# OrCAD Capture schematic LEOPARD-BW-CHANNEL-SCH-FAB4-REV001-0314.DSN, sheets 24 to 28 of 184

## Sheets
24 155_PVTT_CD_MOSFET: size A3; title: PVTT_CD_MOSFET
25 154_PVDDQ_CD_MOSFET: size C; title: PVDDQ_CD_MOSFET
26 153_PVDDQ_CD_Controller: size C; title: PVDDQ_CD_CONTROLLER
27 152_PVPP_AB_TPS53318: size A3; title: PVPP_AB_TPS53318
28 151_PVDDQ_AB_Decoupling: size A3; title: PVDDQ_AB_DECOUPLING

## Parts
sheet 151_PVDDQ_AB_Decoupling
PC285  SCD1U25V5KX-1GP  [C805H54]
PC286  SC1U25V6KX-2GP  [C1206H45]
PC287  SCD1U25V5KX-1GP  [C805H54]
PC288  SE470UF2VDM-GP  [CT7343H83]
PC289  SE470UF2VDM-GP  [CT7343H83]
PC290  SE470UF2VDM-GP  [CT7343H83]
PC291  SE470UF2VDM-GP  [CT7343H83]
PC292  SC47U4V5MX-2-GP  [C805H58]
PC293  SC47U4V5MX-2-GP  [C805H58]
PC294  SC47U4V5MX-2-GP  [C805H58]
PC295  SC47U4V5MX-2-GP  [C805H58]
PC296  SC22U6D3V5MX-5-GP  [C805H56]
PC297  SC22U6D3V5MX-5-GP  [C805H56]
PC298  SC22U6D3V5MX-5-GP  [C805H56]
PC299  SC22U6D3V5MX-5-GP  [C805H56]
PC300  SC22U6D3V5MX-5-GP  [C805H56]
PC301  SC22U6D3V5MX-5-GP  [C805H56]
PC302  SC22U6D3V5MX-5-GP  [C805H56]
PC303  SC22U6D3V5MX-5-GP  [C805H56]
PC304  SC22U6D3V5MX-5-GP  [C805H56]
PC305  SC22U6D3V5MX-5-GP  [C805H56]
PC306  SC22U6D3V5MX-5-GP  [C805H56]
PC307  SC22U6D3V5MX-5-GP  [C805H56]
PC308  SC22U6D3V5MX-5-GP  [C805H56]
PC309  SC22U6D3V5MX-5-GP  [C805H56]
PC310  SC22U6D3V5MX-5-GP  [C805H56]
PC311  SC22U6D3V5MX-5-GP  [C805H56]
PC312  SC22U6D3V5MX-5-GP  [C805H56]
PC313  SC22U6D3V5MX-5-GP  [C805H56]
PC314  SC22U6D3V5MX-5-GP  [C805H56]
PC315  SC22U6D3V5MX-5-GP  [C805H56]
PC316  SC22U6D3V5MX-5-GP  [C805H56]
PC317  SC22U6D3V5MX-5-GP  [C805H56]
PC318  SC22U6D3V5MX-5-GP  [C805H56]
PC319  SC22U6D3V5MX-5-GP  [C805H56]
PC320  SC22U6D3V5MX-5-GP  [C805H56]
PC321  SC22U6D3V5MX-5-GP  [C805H56]
PC322  SC22U6D3V5MX-5-GP  [C805H56]
PC323  SC22U6D3V5MX-5-GP  [C805H56]
PC324  SC22U6D3V5MX-5-GP  [C805H56]
PC325  SC22U6D3V5MX-5-GP  [C805H56]
PC326  SC22U6D3V5MX-5-GP  [C805H56]
PC327  SC22U6D3V5MX-5-GP  [C805H56]
PC328  SC22U6D3V5MX-5-GP  [C805H56]
PC329  SC22U6D3V5MX-5-GP  [C805H56]
PC330  SC22U6D3V5MX-5-GP  [C805H56]
PC331  SC22U6D3V5MX-5-GP  [C805H56]
PC332  SC22U6D3V5MX-5-GP  [C805H56]
PC333  SC22U6D3V5MX-5-GP  [C805H56]
PC334  SC22U6D3V5MX-5-GP  [C805H56]
PC335  SC22U6D3V5MX-5-GP  [C805H56]
PC837  SC22U6D3V5MX-5-GP  [C805H56]
PC838  SC22U6D3V5MX-5-GP  [C805H56]
PC839  SC22U6D3V5MX-5-GP  [C805H56]
PC840  SC22U6D3V5MX-5-GP  [C805H56]
PC841  SC22U6D3V5MX-5-GP  [C805H56]
PC842  SC22U6D3V5MX-5-GP  [C805H56]
PC843  SC22U6D3V5MX-5-GP  [C805H56]
PC844  SC22U6D3V5MX-5-GP  [C805H56]
PC994  SC22U6D3V5MX-5-GP  [C805H56]
PC995  SC22U6D3V5MX-5-GP  [C805H56]
PC996  SC22U6D3V5MX-5-GP  [C805H56]
PL16  IND-65NH-GP  [L4038-1412H158]
PR181  33R3F-L-GP  [R603H22]
PR182  0R2F-L-GP  [R402H16]
PR183  0R2F-L-GP  [R402H16]
PTC5  E270U16VM-28-GP  [ECAP-100D6D3H363]
sheet 152_PVPP_AB_TPS53318
PC336  SC10U16V5KX-1-GP  [C805H54]
PC337  SC10U16V5KX-1-GP  [C805H54]
PC338  SC10U16V5KX-1-GP  [C805H54]
PC339  SC10U16V5KX-1-GP  [C805H54]
PC340  SCD1U16V3KX-3GP  [C603H36]
PC341  SC4D7U25V5KX-1-GP  [C805H58]
PC342  SCD1U50V3KX-GP  [C603H36]
PC343  SC2K2P50V3KX-GP  [C603]
PC344  SC1U10V2KX-4-GP  [C402H22]
PC345  SCD1U16V2KX-3GP  [C402H22]
PC346  SC1KP50V2KX-1GP  [C402H22]
PC347  SCD1U16V3KX-3GP  [C603H36]
PC348  SC22U6D3V5MX-5-GP  [C805H56]
PC349  SC47U4V5MX-2-GP  [C805H58]
PC350  SC47U4V5MX-2-GP  [C805H58]
PC351  SC47U4V5MX-2-GP  [C805H58]
PC352  SC47U4V5MX-2-GP  [C805H58]
PC353  SC47U4V5MX-2-GP  [C805H58]
PC354  SC47U4V5MX-2-GP  [C805H58]
PC1035  SC1U10V2KX-4-GP  [C402H22]
PD22  BZT52-C3V3S-GP  [SOD323AKH38]
PL17  BLM21PG220SN1DGP  [L20125H42]
PL18  IND-2D2UH-242-GP  [L7165-1732H119]
PR184  2D2R3-1-U-GP  [R603H22]
PR185  3D01R5F-GP  [R805H24]
PR186  0R2J-2-GP  [R402H16]
PR188  3K9R2F-GP  [R402H16]
PR189  10R3F-GP  [R603H22]
PR190  100KR2F-L1-GP  [R402H16]
PR191  3D01R5F-GP  [R805H24]
PR192  100KR2F-L1-GP  [R402H16]
PR193  100KR2F-L1-GP  [R402H16]
PR194  866KR2F-GP  [R402H16]
PR195  619KR2F-GP  [R402H16]
PR196  31K6R2F-GP  [R402H16]
PR197  10KR2F-2-GP  [R402H16]
PR198  0R3J-0-U-GP  [R603H22]
PR643  10KR2F-2-GP  [R402H16]
PR798  0R2J-2-GP  [R402H16]
PU18  TPS53318DQPR-GP  [DFN22G6050-G6133H60]
sheet 153_PVDDQ_CD_Controller
PC1389  SC1KP50V2KX-1GP  [C402H22]
PC1390  SC1U10V2KX-4-GP  [C402H22]
PC1391  SCD1U16V2KX-3GP  [C402H22]
PC1392  SC1U10V2KX-4-GP  [C402H22]
PC1393  SCD1U16V2KX-3GP  [C402H22]
PC1397  SC220P50V2KX-3GP  [C402H22]
PC1398  SCD47U25V3KX-3-GP  [C603H36]
PC1399  SC10U4V3MX-3-GP  [C603H40]
PC1400  SC220P50V2KX-3GP  [C402H22]
PC1401  SCD1U16V2KX-3GP  [C402H22]
PC1402  SC220P50V2JN-3GP  [C402H22]
PC1467  SC220P50V2JN-3GP  [C402H22]
PC1621  SC220P50V2JN-3GP  [C402H22]
PC7333  SCD47U6D3V2KX-1-GP  [C402H22]
PC7334  SCD47U6D3V2KX-1-GP  [C402H22]
PQ12  NST3906F3T5G-GP-U  [SOT-1123CBE1006-1H16]
PR1939  0R2J-2-GP  [R402H16]
PR2023  19K1R2F-GP  [R402H16]
PR2024  1KR2F-3-GP  [R402H16]
PR2025  0R2J-2-GP  [R402H16]
PR2030  1KR2F-3-GP  [R402H16]
PR2031  1KR2F-3-GP  [R402H16]
PR2032  0R2J-2-GP  [R402H16]
PR2033  0R2J-2-GP  [R402H16]
PR2034  10R3F-GP  [R603H22]
PR2036  0R2J-2-GP  [R402H16]
PR2037  0R0402-PAD-1-GP  [0R0402-PAD]
PR2040  16KR2F-GP  [R402H16]
PR2041  5K36R2F-GP  [R402H16]
PR2042  549R2F-GP  [R402H16]
PR2043  8K06R2F-GP  [R402H16]
PR2044  10R3F-GP  [R603H22]
PR2045  0R2J-2-GP  [R402H16]
PR2046  0R0402-PAD-1-GP  [0R0402-PAD]
PR2047  100R2F-L1-GP-U  [R402H14]
PR2048  100R2F-L1-GP-U  [R402H14]
PR2049  49D9R2F-GP  [R402H16]
PR2051  0R2J-2-GP  [R402H16]
PR2052  0R2J-2-GP  [R402H16]
PR2053  150R2F-1-GP  [R402H16]
PTP4  TP20B24R10-B-GP  [TP20B24R10-B]
PU19  PX3244HDM-1-GP  [QFN40J5-G3D75H36]
sheet 154_PVDDQ_CD_MOSFET
PC1526  SCD47U25V3KX-3-GP  [C603H36]
PC1527  SC10U16V5KX-1-GP  [C805H54]
PC1528  SC10U16V5KX-1-GP  [C805H54]
PC1529  SC10U16V5KX-1-GP  [C805H54]
PC1530  SCD1U16V2KX-3GP  [C402H22]
PC1531  SC1U25V3KX-GP  [C603H36]
PC1532  SCD1U16V2KX-3GP  [C402H22]
PC1533  SC1U10V2KX-4-GP  [C402H22]
PC1534  SCD22U16V2KX-GP  [C402H22]
PC1535  SC1U10V2KX-4-GP  [C402H22]
PC1536  SCD47U25V3KX-3-GP  [C603H36]
PC1537  SC10U16V5KX-1-GP  [C805H54]
PC1538  SC10U16V5KX-1-GP  [C805H54]
PC1539  SCD1U16V2KX-3GP  [C402H22]
PC1540  SC10U16V5KX-1-GP  [C805H54]
PC1541  SC1U25V3KX-GP  [C603H36]
PC1542  SCD1U16V2KX-3GP  [C402H22]
PC1543  SC1U10V2KX-4-GP  [C402H22]
PC1544  SCD22U16V2KX-GP  [C402H22]
PC1545  SC1U10V2KX-4-GP  [C402H22]
PG66  COPPER-CLOSE-GP-U  [CON2C-U]
PG70  COPPER-CLOSE-GP-U  [CON2C-U]
PG71  COPPER-CLOSE-GP-U  [CON2C-U]
PG72  COPPER-CLOSE-GP-U  [CON2C-U]
PL87  IND-150NH-15-GP  [L102078-254224H296]
PL94  IND-150NH-15-GP  [L102078-254224H296]
PR36  0R2J-2-GP  [R402H16]
PR37  0R2J-2-GP  [R402H16]
PR54  0R2J-2-GP  [R402H16]
PR55  0R2J-2-GP  [R402H16]
PR2211  1R2F-GP  [R402H16]
PR2244  1R2F-GP  [R402H16]
PR2245  10KR2F-2-GP  [R402H16]
PR2246  10KR2F-2-GP  [R402H16]
PR2267  0R3J-6-GP  [R603H22]
PR2270  0R3J-6-GP  [R603H22]
PR6651  562R2F-GP  [R402H16]
PR6652  562R2F-GP  [R402H16]
PR6665  562R2F-GP  [R402H16]
PR6666  562R2F-GP  [R402H16]
PTP31  TPAD24  [TPAD24]
PTP32  TPAD24  [TPAD24]
PTP45  TPAD24  [TPAD24]
PTP46  TPAD24  [TPAD24]
PU190  TDA21232-GP  [QFN31G5-G4P-7H38]
PU197  TDA21232-GP  [QFN31G5-G4P-7H38]
sheet 155_PVTT_CD_MOSFET
PC388  SC1U10V2KX-4-GP  [C402H22]
PC389  SCD22U16V2KX-GP  [C402H22]
PC391  SCD22U16V2KX-GP  [C402H22]
PC393  SC1U25V3KX-GP  [C603H36]
PC396  SC10U16V5KX-1-GP  [C805H54]
PC397  SC10U16V5KX-1-GP  [C805H54]
PC398  SCD47U25V3KX-3-GP  [C603H36]
PC399  SC220P50V2JN-3GP  [C402H22]
PC400  SC47U4V5MX-2-GP  [C805H58]
PC401  SC47U4V5MX-2-GP  [C805H58]
PC402  SC22U6D3V5MX-5-GP  [C805H56]
PC403  SC22U6D3V5MX-5-GP  [C805H56]
PC404  SC22U6D3V5MX-5-GP  [C805H56]
PC405  SC22U6D3V5MX-5-GP  [C805H56]
PC406  SC22U6D3V5MX-5-GP  [C805H56]
PC407  SC22U6D3V5MX-5-GP  [C805H56]
PC408  SC22U6D3V5MX-5-GP  [C805H56]
PC409  SC22U6D3V5MX-5-GP  [C805H56]
PC410  SC22U6D3V5MX-5-GP  [C805H56]
PC411  SC22U6D3V5MX-5-GP  [C805H56]
PC412  SC22U6D3V5MX-5-GP  [C805H56]
PC413  SC22U6D3V5MX-5-GP  [C805H56]
PC414  SE470UF2VDM-GP  [CT7343H83]
PG31  COPPER-CLOSE-GP-U  [CON2C-U]
PG32  COPPER-CLOSE-GP-U  [CON2C-U]
PL21  IND-1UH-101-GP  [L6868-3612H166]
PQ6  NST3906F3T5G-GP-U  [SOT-1123CBE1006-1H16]
PR244  2D2R2F-GP  [R402H16]
PR246  10KR2F-2-GP  [R402H16]
PR247  93K1R2F-L-GP  [R402H16]
PR250  562R2F-GP  [R402H16]
PR251  562R2F-GP  [R402H16]
PR252  0R2F-L-GP  [R402H16]
PR253  0R2F-L-GP  [R402H16]
PR254  120R3F-L-GP  [R603H22]
PR854  0R3J-0-U-GP  [R603H22]
PR855  0R3J-0-U-GP  [R603H22]
PU22  PX3517-GP  [DFN10G3-G2619H36]
PU23  AON7934-GP  [MLP8F3-G2P-1H32]

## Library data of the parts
PC285 PC287 = SCD1U25V5KX-1GP: CHIP CAP0.1U25V K0805 X7R(ROHS; GREENDFACTOR: R2_SA;HF_SA;G_SA;; Package Type: SMD-BCG; Part Number: 78.10422.21L; SPEC: http://wpqssvr.wistron.com.tw:7001/wpqs/servlet/COM.qpart.Attachment?PartNumber=78.10422.21L
PC286 = SC1U25V6KX-2GP: CHIP CAP C 1U 25V K1206 X7R; GREENDFACTOR: R2_SA;HF_SA;G_SA;; Package Type: SMD-BCG1; Part Number: 78.10522.22L; SPEC: http://wpqssvr.wistron.com.tw:7001/wpqs/servlet/COM.qpart.Attachment?PartNumber=78.10522.22L
PC288-PC291 PC414 = SE470UF2VDM-GP: CHIP CAP 470UF 2V EEFSX0D471X; GREENDFACTOR: R_SA;; Module: VR_DDR_P1V5_VDDQ; Package Type: SMD-TCG1; Part Number: 79.47719.2BL; Part Type: SMD-TCG1; Part_Function: Cout_bulk; Part_Spec: 470uF/2V/6mohm; Part_Type: Solid_al_cap; SPEC: http://wpqssvr.wistron.com.tw:7001/wpqs/servlet/COM.qpart.Attachment?PartNumber=79.47719.2BL; VENDOR_PN: EEFSX0D471XE
PC292-PC295 PC349-PC354 PC400 PC401 = SC47U4V5MX-2-GP: CHIP CAP C 47U 4V M0805 X6S; GREENDFACTOR: R2_SA;HF_SA;G_SA;; Package Type: SMD-BCG3; Part Number: 78.4761T.81L; SPEC: http://wpqssvr.wistron.com.tw:7001/wpqs/servlet/COM.qpart.Attachment?PartNumber=78.4761T.81L
PC296-PC335 PC348 PC402-PC413 PC837-PC844 = SC22U6D3V5MX-5-GP: CHIP CAP C 22U 6.3V M0805 X6S; GREENDFACTOR: R2_SA;HF_SA;G_SA;; Package Type: SMD-BCG2; Part Number: 78.22610.81L; SPEC: http://wpqssvr.wistron.com.tw:7001/wpqs/servlet/COM.qpart.Attachment?PartNumber=78.22610.81L
PC994-PC996 = SC22U6D3V5MX-5-GP: CHIP CAP C 22U 6.3V M0805 X6S; GREENDFACTOR: R2_SA;HF_SA;G_SA;; Package Type: SMD-BCG2; Part Number: 78.22610.81L; SPEC: http://wpqssvr.wistron.com.tw:7001/wpqs/servlet/COM.qpart.Attachment?PartNumber=78.22610.81L; Size: 0805; Type: X6S
PL16 = IND-65NH-GP: CHIP IND 65NH FP0404R1-R065-R; GREENDFACTOR: R2_SA;; Part Number: 68.650CN.101; Part Type: DISCRET-G6; SPEC: http://wpqssvr.wistron.com.tw:7001/wpqs/servlet/COM.qpart.Attachment?PartNumber=68.650CN.101
PR181 = 33R3F-L-GP: CHIP RES 33 F 1/10W 0603; GREENDFACTOR: R2_SA;HF_SA;G_SA;; Package Type: SMD-RG; Part Number: 64.33R05.55L; SPEC: http://wpqssvr.wistron.com.tw:7001/wpqs/servlet/COM.qpart.Attachment?PartNumber=64.33R05.55L
PR182 PR183 PR252 PR253 = 0R2F-L-GP: CHIP RES 0 F 0402 RK73Z1ETTP KOA; GREENDFACTOR: R2_SA;; Package Type: SMD-RG5; Part Number: 64.R0005.L0L; SPEC: http://wpqssvr.wistron.com.tw:7001/wpqs/servlet/COM.qpart.Attachment?PartNumber=64.R0005.L0L
PTC5 = E270U16VM-28-GP: CAP EL 270U 16V RT2.5 6.3*8 SOLID CAP; GREENDFACTOR: R2_SA;HF_SA;; Part Number: 09.2771D.E4L; Part Spec: 270uF/16V/10mohm/5A; Part Type: DIP-TCG4; SPEC: http://wpqssvr.wistron.com.tw:7001/wpqs/servlet/COM.qpart.Attachment?PartNumber=09.2771D.E4L
PC336-PC339 PC396 PC397 PC1527-PC1529 PC1537 PC1538 PC1540 = SC10U16V5KX-1-GP: CHIP CAP C 10U 16V K0805 X6S; GREENDFACTOR: R2_SA;; Package Type: SMD-BCG5; Part Number: 78.10621.81L; SPEC: http://wpqssvr.wistron.com.tw:7001/wpqs/servlet/COM.qpart.Attachment?PartNumber=78.10621.81L
PC340 PC347 = SCD1U16V3KX-3GP: CHIP CAP 0.1U16V K0603 X7R(ROH; GREENDFACTOR: R2_SA;R_SA;HF_SA;G_SA;; Module: VR_SYSTEM_P1V8; Package Type: SMD-BCG; Part Number: 78.10421.2BL; SPEC: http://wpqssvr.wistron.com.tw:7001/wpqs/servlet/COM.qpart.Attachment?PartNumber=78.10421.2BL; Size: 0603; Type: X7R
PC341 = SC4D7U25V5KX-1-GP: CHIP CAP C 4.7U 25V K0805 X7R; GREENDFACTOR: R2_SA;HF_SA;G_SA;; Package Type: SMD-BCG4; Part Number: 078.47522.0211; SPEC: http://wpqssvr.wistron.com.tw:7001/wpqs/servlet/COM.qpart.Attachment?PartNumber=078.47522.0211
PC342 = SCD1U50V3KX-GP: CHIP CAP C 0.1U 50V K0603 X7R; GREENDFACTOR: R2_SA;HF_SA;G_SA;; Level: SMD; MAIN_SOURCE: M; Package Type: RCL_GP; Part Number: 78.10424.2BL; Part Type: RCL_GP; SPEC: http://wpqssvr.wistron.com.tw:7001/wpqs/servlet/COM.qpart.Attachment?PartNumber=78.10424.2BL; Status: POP
PC343 = SC2K2P50V3KX-GP: CHIP CAP C 2200P 50V K0603 X7R; GREENDFACTOR: R2_SA;HF_SA;G_SA;; Level: SMD; POP?: NOPOP; Package Type: SMD-BCG6; Part Number: 78.22224.2BL; Part Type: SMD-BCG6; SPEC: http://wpqssvr.wistron.com.tw:7001/wpqs/servlet/COM.qpart.Attachment?PartNumber=78.22224.2BL; Status: POP
PC344 PC388 PC1390 PC1392 PC1533 PC1535 PC1543 PC1545 = SC1U10V2KX-4-GP: CHIP CAP C 1U 10V K 0402 X6S; GREENDFACTOR: R2_SA;HF_SA;; Package Type: SMD-BCG6; Part Number: 78.10523.8FL; SPEC: http://wpqssvr.wistron.com.tw:7001/wpqs/servlet/COM.qpart.Attachment?PartNumber=78.10523.8FL
PC345 PC1401 = SCD1U16V2KX-3GP: CHIP CAP C 0.1U 16V K0402 X7R; CATEGORIES: CAP_1.xV; GREENDFACTOR: R2_SA;HF_SA;G_SA;; MAIN_SOURCE: M; Part Number: 78.10421.2FL; Part Type: SMD-BCG; SPEC: http://wpqssvr.wistron.com.tw:7001/wpqs/servlet/COM.qpart.Attachment?PartNumber=78.10421.2FL
PC346 = SC1KP50V2KX-1GP: CHIP CAP 1000P50V K0402 X7R(RO; GREENDFACTOR: R2_SA;HF_SA;G_SA;; Level: SMD; MAIN_SOURCE: M; Package Type: SMD-BCG; Part Number: 78.10224.2FL; Part Type: SMD-BCG; SPEC: http://wpqssvr.wistron.com.tw:7001/wpqs/servlet/COM.qpart.Attachment?PartNumber=78.10224.2FL; Status: POP
PC1035 = SC1U10V2KX-4-GP: CHIP CAP C 1U 10V K 0402 X6S; GREENDFACTOR: R2_SA;HF_SA;; POP?: NOPOP; Package Type: SMD-BCG6; Part Number: 78.10523.8FL; SPEC: http://wpqssvr.wistron.com.tw:7001/wpqs/servlet/COM.qpart.Attachment?PartNumber=78.10523.8FL
PD22 = BZT52-C3V3S-GP: DIODE ZEN BZT52-C3V3S 3.3V SOD-323; GREENDFACTOR: R2_SA;; Part Number: 83.3R303.G3F; Part Type: DISCRET-G4; SPEC: http://wpqssvr.wistron.com.tw:7001/wpqs/servlet/COM.qpart.Attachment?PartNumber=83.3R303.G3F
PL17 = BLM21PG220SN1DGP: CHIP BEAD BLM21PG220SN1D (LF); GREENDFACTOR: R2_SA;HF_SA;; Level: SMD; Package Type: DISCRET-G; Part Number: 68.00084.831; Part Type: DISCRET-G; SPEC: http://wpqssvr.wistron.com.tw:7001/wpqs/servlet/COM.qpart.Attachment?PartNumber=68.00084.831; Status: POP
PL18 = IND-2D2UH-242-GP: CHIP IND 2.2UH M SPM6530T-2R2M; GREENDFACTOR: R2_SA;HF_SA;; Package Type: DISCRET-G6; Part Number: 68.2R21E.10X; SPEC: http://wpqssvr.wistron.com.tw:7001/wpqs/servlet/COM.qpart.Attachment?PartNumber=68.2R21E.10X
PR184 = 2D2R3-1-U-GP: CHIP RES 2.2 F 1/10W 0603(ROHS; GREENDFACTOR: R2_SA;HF_SA;G_SA;; Package Type: RCL_GP; Part Number: 64.2R205.55L; SPEC: http://wpqssvr.wistron.com.tw:7001/wpqs/servlet/COM.qpart.Attachment?PartNumber=64.2R205.55L
PR185 = 3D01R5F-GP: CHIP RES 3.01 F 1/8W 0805; GREENDFACTOR: R2_SA;HF_SA;G_SA;; Level: SMD; Package Type: SMD-RG5; Part Number: 64.3R015.16L; Part Type: SMD-RG5; SPEC: http://wpqssvr.wistron.com.tw:7001/wpqs/servlet/COM.qpart.Attachment?PartNumber=64.3R015.16L; Status: POP
PR186 PR798 = 0R2J-2-GP: CHIP RES 0 J 1/16W 0402; GREENDFACTOR: R2_SA;HF_SA;G_SA;; Level: SMD; Package Type: SMD-RG; Part Number: 63.R0034.1DL; Part Type: SMD-RG; ROOM: VR_CHIPSET; SPEC: http://wpqssvr.wistron.com.tw:7001/wpqs/servlet/COM.qpart.Attachment?PartNumber=63.R0034.1DL; Status: POP
PR188 = 3K9R2F-GP: CHIP RES 3.9K F 1/16W 0402; GREENDFACTOR: R2_SA;HF_SA;G_SA;; Package Type: RCL_GP; Part Number: 64.39015.6DL; SPEC: http://wpqssvr.wistron.com.tw:7001/wpqs/servlet/COM.qpart.Attachment?PartNumber=64.39015.6DL
PR189 PR2034 PR2044 = 10R3F-GP: CHIP RES 10 F 1/10W 0603; GREENDFACTOR: R2_SA;HF_SA;G_SA;; Level: SMD; Package Type: RCL_GP; Part Number: 64.10R05.55L; Part Type: RCL_GP; SPEC: http://wpqssvr.wistron.com.tw:7001/wpqs/servlet/COM.qpart.Attachment?PartNumber=64.10R05.55L; Status: POP
PR190 = 100KR2F-L1-GP: CHIP RES 100K F 1/16W 0402; GREENDFACTOR: R2_SA;HF_SA;G_SA;; Part Number: 64.10035.6DL; Part Type: SMD-RG; SPEC: http://wpqssvr.wistron.com.tw:7001/wpqs/servlet/COM.qpart.Attachment?PartNumber=64.10035.6DL
PR191 = 3D01R5F-GP: CHIP RES 3.01 F 1/8W 0805; GREENDFACTOR: R2_SA;HF_SA;G_SA;; Level: SMD; POP?: NOPOP; Package Type: SMD-RG5; Part Number: 64.3R015.16L; Part Type: SMD-RG5; SPEC: http://wpqssvr.wistron.com.tw:7001/wpqs/servlet/COM.qpart.Attachment?PartNumber=64.3R015.16L; Status: POP
PR192 = 100KR2F-L1-GP: CHIP RES 100K F 1/16W 0402; GREENDFACTOR: R2_SA;HF_SA;G_SA;; Level: SMD; POP?: NOPOP; Package Type: SMD-RG; Part Number: 64.10035.6DL; Part Type: SMD-RG; SPEC: http://wpqssvr.wistron.com.tw:7001/wpqs/servlet/COM.qpart.Attachment?PartNumber=64.10035.6DL; Status: NOPOP
PR193 = 100KR2F-L1-GP: CHIP RES 100K F 1/16W 0402; GREENDFACTOR: R2_SA;HF_SA;G_SA;; Package Type: SMD-RG; Part Number: 64.10035.6DL; SPEC: http://wpqssvr.wistron.com.tw:7001/wpqs/servlet/COM.qpart.Attachment?PartNumber=64.10035.6DL
PR194 = 866KR2F-GP: CHP RES 866K F 1/16W 0402; GREENDFACTOR: R2_SA;HF_SA;G_SA;; Level: SMD; POP?: NOPOP; Package Type: SMD-RG4; Part Number: 64.86635.6DL; Part Type: SMD-RG4; SPEC: http://wpqssvr.wistron.com.tw:7001/wpqs/servlet/COM.qpart.Attachment?PartNumber=64.86635.6DL; Status: POP
PR195 = 619KR2F-GP: CHIP RES 619K F 1/16W 0402; GREENDFACTOR: R2_SA;HF_SA;G_SA;; Level: SMD; POP?: NOPOP; Package Type: SMD-RG3; Part Number: 64.61935.6DL; Part Type: SMD-RG3; SPEC: http://wpqssvr.wistron.com.tw:7001/wpqs/servlet/COM.qpart.Attachment?PartNumber=64.61935.6DL; Status: NOPOP
PR196 = 31K6R2F-GP: CHIP RES 31.6K F 1/16W 0402; GREENDFACTOR: R2_SA;HF_SA;G_SA;; Package Type: RCL_GP; Part Number: 64.31625.6DL; SPEC: http://wpqssvr.wistron.com.tw:7001/wpqs/servlet/COM.qpart.Attachment?PartNumber=64.31625.6DL
PR197 = 10KR2F-2-GP: CHIP RES 10K F 1/16W 0402; GREENDFACTOR: R2_SA;HF_SA;G_SA;; Package Type: SMD-RG; Part Number: 64.10025.6DL; SPEC: http://wpqssvr.wistron.com.tw:7001/wpqs/servlet/COM.qpart.Attachment?PartNumber=64.10025.6DL
PR198 PR854 PR855 = 0R3J-0-U-GP: CHIP RES 0 J 1/10W 0603; GREENDFACTOR: R2_SA;HF_SA;G_SA;; Package Type: RCL_GP; Part Number: 63.00000.00L; SPEC: http://wpqssvr.wistron.com.tw:7001/wpqs/servlet/COM.qpart.Attachment?PartNumber=63.00000.00L
PR643 = 10KR2F-2-GP: CHIP RES 10K F 1/16W 0402; GREENDFACTOR: R2_SA;HF_SA;G_SA;; Level: SMD; Package Type: SMD-RG; Part Number: 64.10025.6DL; Part Type: SMD-RG; SPEC: http://wpqssvr.wistron.com.tw:7001/wpqs/servlet/COM.qpart.Attachment?PartNumber=64.10025.6DL
PU18 = TPS53318DQPR-GP: IC PWR CTRL TPS53318DQPR QFN 22P; GREENDFACTOR: R2_C;HF_C;; Package Type: DISCRET-G5; Part Number: 74.53318.073; SPEC: http://wpqssvr.wistron.com.tw:7001/wpqs/servlet/COM.qpart.Attachment?PartNumber=74.53318.073
PC1389 = SC1KP50V2KX-1GP: CHIP CAP 1000P50V K0402 X7R(RO; GREENDFACTOR: R2_SA;HF_SA;G_SA;; MAIN_SOURCE: M; Package Type: SMD-BCG; Part Number: 78.10224.2FL; SPEC: http://wpqssvr.wistron.com.tw:7001/wpqs/servlet/COM.qpart.Attachment?PartNumber=78.10224.2FL
PC1391 PC1393 = SCD1U16V2KX-3GP: CHIP CAP C 0.1U 16V K0402 X7R; GREENDFACTOR: R2_SA;HF_SA;G_SA;; MAIN_SOURCE: M; Package Type: SMD-BCG; Part Number: 78.10421.2FL; SPEC: http://wpqssvr.wistron.com.tw:7001/wpqs/servlet/COM.qpart.Attachment?PartNumber=78.10421.2FL
PC1397 PC1400 = SC220P50V2KX-3GP: CHIP CAP 220P50V K0402 X7R(ROH; GREENDFACTOR: R2_SA;HF_SA;G_SA;; MAIN_SOURCE: M; Package Type: SMD-BCG; Part Number: 78.22124.2FL; SPEC: http://wpqssvr.wistron.com.tw:7001/wpqs/servlet/COM.qpart.Attachment?PartNumber=78.22124.2FL
PC398 PC1398 PC1526 PC1536 = SCD47U25V3KX-3-GP: CHIP CAP C 0.47U 25V K0603 X7R; GREENDFACTOR: R2_SA;HF_SA;G_SA;; Part Number: 78.47422.2BL; Part Type: SMD-BCG5; SPEC: http://wpqssvr.wistron.com.tw:7001/wpqs/servlet/COM.qpart.Attachment?PartNumber=78.47422.2BL
PC1399 = SC10U4V3MX-3-GP: CHIP CAP C 10U 4V M0603 X6S; GREENDFACTOR: R2_C;; POP?: 078.1061T.08B1; Package Type: SMD-BCG6; Part Number: 78.1061T.8BL; SPEC: http://wpqssvr.wistron.com.tw:7001/wpqs/servlet/COM.qpart.Attachment?PartNumber=78.1061T.8BL
PC399 PC1402 PC1467 PC1621 = SC220P50V2JN-3GP: CHIP CAP C 220P 50V J0402 NPO; GREENDFACTOR: R2_SA;HF_SA;G_SA;; Package Type: SMD-BCG; Part Number: 78.22134.1FL; SPEC: http://wpqssvr.wistron.com.tw:7001/wpqs/servlet/COM.qpart.Attachment?PartNumber=78.22134.1FL
PC7333 PC7334 = SCD47U6D3V2KX-1-GP: CHIP CAP C 0.47U 6.3V K 0402 X6S; GREENDFACTOR: R2_SA;HF_SA;; Package Type: SMD-BCG3; Part Number: 78.47420.8FL; SPEC: http://wpqssvr.wistron.com.tw:7001/wpqs/servlet/COM.qpart.Attachment?PartNumber=78.47420.8FL
PQ6 PQ12 = NST3906F3T5G-GP-U: XTOR NST3906F3T5G PNP SOT-1123; GREENDFACTOR: R2_SA;HF_SA;; Package Type: DISCRET-G5; Part Number: 84.03906.01K; SPEC: http://wpqssvr.wistron.com.tw:7001/wpqs/servlet/COM.qpart.Attachment?PartNumber=84.03906.01K
PR1939 PR2045 = 0R2J-2-GP: CHIP RES 0 J 1/16W 0402; GREENDFACTOR: R2_SA;HF_SA;G_SA;; Part Number: 63.R0034.1DL; Part Type: SMD-RG; SPEC: http://wpqssvr.wistron.com.tw:7001/wpqs/servlet/COM.qpart.Attachment?PartNumber=63.R0034.1DL
PR2023 = 19K1R2F-GP: CHIP RES 19.1K F 1/16W 0402; GREENDFACTOR: R2_SA;HF_SA;G_SA;; Part Number: 64.19125.6DL; Part Type: RCL_GP; SPEC: http://wpqssvr.wistron.com.tw:7001/wpqs/servlet/COM.qpart.Attachment?PartNumber=64.19125.6DL
PR2024 PR2030 PR2031 = 1KR2F-3-GP: CHIP RES 1K F 1/16W 0402; GREENDFACTOR: R2_SA;HF_SA;G_SA;; Package Type: SMD-RG; Part Number: 64.10015.6DL; SPEC: http://wpqssvr.wistron.com.tw:7001/wpqs/servlet/COM.qpart.Attachment?PartNumber=64.10015.6DL
PR54 PR55 PR2025 PR2032 PR2033 PR2036 PR2051 PR2052 = 0R2J-2-GP: CHIP RES 0 J 1/16W 0402; GREENDFACTOR: R2_SA;HF_SA;G_SA;; Package Type: SMD-RG; Part Number: 63.R0034.1DL; SPEC: http://wpqssvr.wistron.com.tw:7001/wpqs/servlet/COM.qpart.Attachment?PartNumber=63.R0034.1DL
PR2037 PR2046 = 0R0402-PAD-1-GP: DUMMY PAD WITH WIRE RES 0 0402; GREENDFACTOR: R_C;; Module: VR_CPU_PVCC; Package Type: SMD-RG2; Part Number: ZZ.R0402.001; Part Type: SMD-RG2; Quotation: 8_1; SPEC: http://wpqssvr.wistron.com.tw:7001/wpqs/servlet/COM.qpart.Attachment?PartNumber=ZZ.R0402.001
PR2040 = 16KR2F-GP: CHIP RES 16K F 1/16W 0402; GREENDFACTOR: R2_SA;HF_SA;G_SA;; Module: VR_PVCORE_CPU; POP?: NOPOP; Package Type: SMD-RG; Part Number: 64.16025.6DL; Quotation: 8_1; SPEC: http://wpqssvr.wistron.com.tw:7001/wpqs/servlet/COM.qpart.Attachment?PartNumber=64.16025.6DL
PR2041 = 5K36R2F-GP: CHIP RES 5.36K F 1/16W 0402; GREENDFACTOR: R2_SA;HF_SA;G_SA;; Package Type: SMD-RG; Part Number: 64.53615.6DL; SPEC: http://wpqssvr.wistron.com.tw:7001/wpqs/servlet/COM.qpart.Attachment?PartNumber=64.53615.6DL
PR2042 = 549R2F-GP: CHIP RES 549 F 1/16W 0402; GREENDFACTOR: R2_SA;HF_SA;; Package Type: RCL_GP; Part Number: 64.54905.6DL; SPEC: http://wpqssvr.wistron.com.tw:7001/wpqs/servlet/COM.qpart.Attachment?PartNumber=64.54905.6DL
PR2043 = 8K06R2F-GP: CHIP RES 8.06K F 1/16W 0402; GREENDFACTOR: R2_SA;HF_SA;G_SA;; Part Number: 64.80615.6DL; Part Type: RCL_GP; SPEC: http://wpqssvr.wistron.com.tw:7001/wpqs/servlet/COM.qpart.Attachment?PartNumber=64.80615.6DL
PR2047 = 100R2F-L1-GP-U: CHIP RES 100 F 1/16W 0402; GREENDFACTOR: R2_SA;HF_SA;G_SA;; POP?: NOPOP; Package Type: SMD-RG; Part Number: 64.10005.6DL; SPEC: http://wpqssvr.wistron.com.tw:7001/wpqs/servlet/COM.qpart.Attachment?PartNumber=64.10005.6DL
PR2048 = 100R2F-L1-GP-U: CHIP RES 100 F 1/16W 0402; GREENDFACTOR: R2_SA;HF_SA;G_SA;; Package Type: SMD-RG; Part Number: 64.10005.6DL; SPEC: http://wpqssvr.wistron.com.tw:7001/wpqs/servlet/COM.qpart.Attachment?PartNumber=64.10005.6DL
PR2049 = 49D9R2F-GP: CHIP RES 49.9 F 1/16W 0402; GREENDFACTOR: R2_SA;HF_SA;G_SA;; Package Type: RCL_GP; Part Number: 64.49R95.6DL; SPEC: http://wpqssvr.wistron.com.tw:7001/wpqs/servlet/COM.qpart.Attachment?PartNumber=64.49R95.6DL
PR2053 = 150R2F-1-GP: CHIP RES 150 F 1/16W 0402; GREENDFACTOR: R2_SA;HF_SA;G_SA;; Package Type: SMD-RG; Part Number: 64.15005.6DL; SPEC: http://wpqssvr.wistron.com.tw:7001/wpqs/servlet/COM.qpart.Attachment?PartNumber=64.15005.6DL
PTP4 = TP20B24R10-B-GP_4: TEST VIA FOR DRILL 10MIL; GREENDFACTOR: R2_C;; Package Type: DISCRET-G5; Part Number: ZZ.0TPAD.211; SPEC: http://wpqssvr.wistron.com.tw:7001/wpqs/servlet/COM.qpart.Attachment?PartNumber=ZZ.0TPAD.211
PU19 = PX3244HDM-1-GP: IC CONVERTER PX3244HDM QFN 40P; GREENDFACTOR: R2_SA;; Part Number: 074.03244.0043; Part Type: ASIC-G5; SPEC: http://wpqssvr.wistron.com.tw:7001/wpqs/servlet/COM.qpart.Attachment?PartNumber=074.03244.0043
PC1530 PC1532 PC1539 PC1542 = SCD1U16V2KX-3GP: CHIP CAP C 0.1U 16V K0402 X7R; GREENDFACTOR: R2_SA;HF_SA;G_SA;; MAIN_SOURCE: M; Package Type: SMD-BCG; Part Number: 78.10421.2FL; SPEC: http://wpqssvr.wistron.com.tw:7001/wpqs/servlet/COM.qpart.Attachment?PartNumber=78.10421.2FL; Size: 0402; Type: X7R
PC393 PC1531 PC1541 = SC1U25V3KX-GP: CHIP CAP C 1U 25V K0603 X7R; GREENDFACTOR: R2_SA;HF_SA;G_SA;; Package Type: SMD-BCG; Part Number: 78.10522.2BL; SPEC: http://wpqssvr.wistron.com.tw:7001/wpqs/servlet/COM.qpart.Attachment?PartNumber=78.10522.2BL
PC389 PC391 PC1534 PC1544 = SCD22U16V2KX-GP: CHIP CAP C 0.22U 16V K0402 X7R; GREENDFACTOR: R2_SA;HF_SA;G_SA;; Package Type: SMD-BCG4; Part Number: 78.22421.2FL; SPEC: http://wpqssvr.wistron.com.tw:7001/wpqs/servlet/COM.qpart.Attachment?PartNumber=78.22421.2FL; Size: 0402; Type: X7R
PG31 PG32 PG66 PG70-PG72 = COPPER-CLOSE-GP-U: COPPER CLOSE; GREENDFACTOR: Regular;; Package Type: DISCRET-G9; Part Number: ZZ.CON2C.XXX; SPEC: http://wpqssvr.wistron.com.tw:7001/wpqs/servlet/COM.qpart.Attachment?PartNumber=ZZ.CON2C.XXX
PL87 PL94 = IND-150NH-15-GP: CHIP IND 150NH K FP1007R3-R15-R; GREENDFACTOR: R2_SA;; Part Number: 68.1512N.10E; Part Type: DISCRET-G9; SPEC: http://wpqssvr.wistron.com.tw:7001/wpqs/servlet/COM.qpart.Attachment?PartNumber=68.1512N.10E
PR36 PR37 = 0R2J-2-GP: CHIP RES 0 J 1/16W 0402; GREENDFACTOR: R2_SA;HF_SA;G_SA;; POP?: NOPOP; Package Type: SMD-RG; Part Number: 63.R0034.1DL; SPEC: http://wpqssvr.wistron.com.tw:7001/wpqs/servlet/COM.qpart.Attachment?PartNumber=63.R0034.1DL
PR2211 PR2244 = 1R2F-GP: CHIP RES 1 F 1/16W 0402; GREENDFACTOR: R2_SA;HF_SA;G_SA;; Package Type: SMD-RG; Part Number: 64.1R005.6DL; SPEC: http://wpqssvr.wistron.com.tw:7001/wpqs/servlet/COM.qpart.Attachment?PartNumber=64.1R005.6DL
PR246 PR2245 PR2246 = 10KR2F-2-GP: CHIP RES 10K F 1/16W 0402; GREENDFACTOR: R2_SA;HF_SA;G_SA;; POP?: NOPOP; Package Type: SMD-RG; Part Number: 64.10025.6DL; SPEC: http://wpqssvr.wistron.com.tw:7001/wpqs/servlet/COM.qpart.Attachment?PartNumber=64.10025.6DL
PR2267 PR2270 = 0R3J-6-GP: CHIP RES 0 J 1/10W 0603; GREENDFACTOR: R2_SA;HF_SA;G_SA;; Part Number: 63.R0033.15L; Part Type: SMD-RG1; SPEC: http://wpqssvr.wistron.com.tw:7001/wpqs/servlet/COM.qpart.Attachment?PartNumber=63.R0033.15L
PR250 PR251 PR6651 PR6652 PR6665 PR6666 = 562R2F-GP: CHIP RES 562 F 1/16W 0402; GREENDFACTOR: R2_SA;HF_SA;G_SA;; Package Type: SMD-RG; Part Number: 64.56205.6DL; SPEC: http://wpqssvr.wistron.com.tw:7001/wpqs/servlet/COM.qpart.Attachment?PartNumber=64.56205.6DL
PTP31 PTP32 PTP45 PTP46 = TPAD24: 24 MILS TEST PAD; GREENDFACTOR: Regular;; Package Type: DISCRET2; Part Number: ZZ.PAD24.001; SPEC: http://wpqssvr.wistron.com.tw:7001/wpqs/servlet/COM.qpart.Attachment?PartNumber=ZZ.PAD24.001
PU190 PU197 = TDA21232-GP: IC PWM TDA21232 IQFN 32P; GREENDFACTOR: R2_C;; Part Number: 074.21232.0073; Part Type: DISCRET-GB1; SPEC: http://wpqssvr.wistron.com.tw:7001/wpqs/servlet/COM.qpart.Attachment?PartNumber=074.21232.0073
PL21 = IND-1UH-101-GP: CHIP IND 1UH HCP0704-1R0-R; GREENDFACTOR: R2_SA;; Package Type: DISCRET-G6; Part Number: 68.1R090.10B; Part_Spec: 1.0uH/6.2mohm/17A; SPEC: http://wpqssvr.wistron.com.tw:7001/wpqs/servlet/COM.qpart.Attachment?PartNumber=68.1R090.10B; Vendor_PN: HCP0704-1R0-R
PR244 = 2D2R2F-GP: CHIP RES 2.2 F 1/16W 0402; GREENDFACTOR: R2_SA;HF_SA;G_SA;; Package Type: SMD-RG1; Part Number: 64.2R205.6DL; SPEC: http://wpqssvr.wistron.com.tw:7001/wpqs/servlet/COM.qpart.Attachment?PartNumber=64.2R205.6DL
PR247 = 93K1R2F-L-GP: CHIP RES 93.1K F 1/16W 0402; GREENDFACTOR: R2_SA;HF_SA;G_SA;; Package Type: SMD-RG; Part Number: 64.93125.6DL; SPEC: http://wpqssvr.wistron.com.tw:7001/wpqs/servlet/COM.qpart.Attachment?PartNumber=64.93125.6DL
PR254 = 120R3F-L-GP: CHIP RES 120 F 1/10W 0603; GREENDFACTOR: R2_SA;HF_SA;G_SA;; Package Type: SMD-RG; Part Number: 64.12005.55L; SPEC: http://wpqssvr.wistron.com.tw:7001/wpqs/servlet/COM.qpart.Attachment?PartNumber=64.12005.55L
PU22 = PX3517-GP: IC MOS DRV PX3517 DFN 10P; GREENDFACTOR: R2_C;; Module: VR_PVCORE_CPU; Package Type: DISCRET-G9; Part Number: 74.03517.0E3; Quotation: 8_1; SPEC: http://wpqssvr.wistron.com.tw:7001/wpqs/servlet/COM.qpart.Attachment?PartNumber=74.03517.0E3
PU23 = AON7934-GP: FET MOS AON7934 NC POWER DFN3X3A; GREENDFACTOR: R2_SA;HF_SA;; Part Number: 84.07934.037; Part Type: DISCRET-G7; SPEC: http://wpqssvr.wistron.com.tw:7001/wpqs/servlet/COM.qpart.Attachment?PartNumber=84.07934.037

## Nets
AGND_PVPP_AB: PR192.1 PR193.1 PR195.1 PR197.2 PR198.1 PR798.2
GND: PC285.2 PC286.2 PC287.2 PC288.2 PC289.2 PC290.2 PC291.2 PC292.2 PC293.2 PC294.2 PC295.2 PC296.2 PC297.2 PC298.2 PC299.2 PC300.2 PC301.2 PC302.2 PC303.2 PC304.2 PC305.2 PC306.2 PC307.2 PC308.2 PC309.2 PC310.2 PC311.2 PC312.2 PC313.2 PC314.2 PC315.2 PC316.2 PC317.2 PC318.2 PC319.2 PC320.2 PC321.2 PC322.2 PC323.2 PC324.2 PC325.2 PC326.2 PC327.2 PC328.2 PC329.2 PC330.2 PC331.2 PC332.2 PC333.2 PC334.2 PC335.2 PC336.2 PC337.2 PC338.2 PC339.2 PC340.2 PC341.2 PC344.1 PC347.2 PC348.2 PC349.2 PC350.2 PC351.2 PC352.2 PC353.2 PC354.2 PC388.2 PC389.2 PC391.2 PC393.2 PC396.2 PC397.2 PC399.1 PC400.2 PC401.2 PC402.2 PC403.2 PC404.2 PC405.2 PC406.2 PC407.2 PC408.2 PC409.2 PC410.2 PC411.2 PC412.2 PC413.2 PC414.2 PC837.2 PC838.2 PC839.2 PC840.2 PC841.2 PC842.2 PC843.2 PC844.2 PC994.2 PC995.2 PC996.2 PC1035.1 PC1389.2 PC1390.2 PC1391.2 PC1392.2 PC1393.2 PC1399.2 PC1401.2 PC1402.1 PC1467.1 PC1527.2 PC1528.2 PC1529.2 PC1530.2 PC1531.2 PC1532.2 PC1533.1 PC1534.1 PC1535.1 PC1537.2 PC1538.2 PC1539.2 PC1540.2 PC1541.2 PC1542.2 PC1543.1 PC1544.1 PC1545.1 PC1621.1 PD22.A(ANODE) PQ6.B PQ6.C PQ12.B PQ12.C PR36.2 PR37.2 PR181.2 PR183.1 PR191.2 PR198.2 PR247.1 PR253.1 PR254.2 PR2024.2 PR2040.1 PR2041.1 PR2043.1 PTC5.2 PU18.23(GND) PU19.1(BVR_READY) PU19.22(ISEN3N) PU19.37(DNC#37) PU19.41(GND) PU22.5(GND) PU22.11(GND) PU23.5(S2#5) PU23.6(S2#6) PU23.7(S2#7) PU190.4(AGND) PU190.12(PGND) PU190.13(PGND) PU190.14(PGND) PU190.15(PGND) PU190.28(PGND) PU190.32(PGND) PU190.34(PGND) PU197.4(AGND) PU197.12(PGND) PU197.13(PGND) PU197.14(PGND) PU197.15(PGND) PU197.28(PGND) PU197.32(PGND) PU197.34(PGND) ; also on sheet 1 2 3 4 5 6 7 8 9 10 11 12 13 14 15 16 17 18 19 20 21 22 23 29 30 31 32 33 34 35 36 37 38 39 44 46 47 49 50 51 52 53 54 55 56 57 58 59 60 61 62 63 64 65 66 69 70 71 73 74 75 76 78 79 80 81 82 83 84 86 87 88 89 90 91 92 93 94 95 96 97 98 99 100 101 102 103 104 105 106 107 108 109 110 111 112 113 114 115 116 117 118 119 128 129 138 139 159 160 161 166 168 169 170 171 172 173 174 175 176 177 180 181 182 183 184
P3V3_STBY: PR54.2 PR55.2 PR643.1 PR2025.1 PR2030.1 PR2031.1 ; also on sheet 2 3 5 6 8 9 10 11 12 15 16 17 20 21 22 30 31 33 34 35 37 38 39 45 47 49 50 51 52 54 55 59 60 61 62 63 64 65 66 69 70 71 72 73 74 76 79 83 84 87 88 89 90 91 92 93 94 95 96 97 98 99 159 161 166 168 173 174 176 177 179 180 182 183 184
P5V_STBY: PC1534.2 PC1535.2 PC1544.2 PC1545.2 PR244.1 PR2211.1 PR2244.1 PU190.29(PVCC) PU197.29(PVCC) ; also on sheet 4 5 6 8 14 15 19 20 29 30 33 34 37 38 59 61 65 69 76 95
P12V_STBY: PC285.1 PC286.1 PL16.1 PL17.1 PR184.1 ; also on sheet 2 3 4 7 9 10 11 12 13 17 18 22 23 32 36 59 60 75 95 104 105 106 107 108 109 110 111 112 113 114 115 116 117 118 119
PVCCIO: PC1399.1 PC1401.1 PR2047.1 PR2048.1 PR2049.1 ; also on sheet 11 16 35 39 46 47 68 87 97 100 101 102 103 120 129 130 139 160 173 177 179 182
PVDDQ_AB: PC288.1 PC289.1 PC290.1 PC291.1 PC292.1 PC293.1 PC294.1 PC295.1 PC296.1 PC297.1 PC298.1 PC299.1 PC300.1 PC301.1 PC302.1 PC303.1 PC304.1 PC305.1 PC306.1 PC307.1 PC308.1 PC309.1 PC310.1 PC311.1 PC312.1 PC313.1 PC314.1 PC315.1 PC316.1 PC317.1 PC318.1 PC319.1 PC320.1 PC321.1 PC322.1 PC323.1 PC324.1 PC325.1 PC326.1 PC327.1 PC328.1 PC329.1 PC330.1 PC331.1 PC332.1 PC333.1 PC334.1 PC335.1 PC837.1 PC838.1 PC839.1 PC840.1 PC841.1 PC842.1 PC843.1 PC844.1 PC994.1 PC995.1 PC996.1 PR181.1 PR182.1 ; also on sheet 30 45 52 97 116 117 118 119 130 139
PVDDQ_AB_VIN: PC287.1 PL16.2 PTC5.1 ; also on sheet 29 30 31
PVDDQ_AB_VSENN_R: PR183.2 ; also on sheet 31
PVDDQ_AB_VSENP_R: PR182.2 ; also on sheet 31
PVDDQ_CD: PG70.2 PG72.2 PL87.2(F) PL94.2(F) ; also on sheet 23 45 97 112 113 114 115 130 139
PVDDQ_CD_ALERT: PR2051.1 PU19.13(ALERT#)
PVDDQ_CD_BOOT1: PR2267.1 PU190.5(BOOT)
PVDDQ_CD_BOOT2: PR2270.1 PU197.5(BOOT)
PVDDQ_CD_EN: PR2032.2 PU19.8(VR_EN)
PVDDQ_CD_EN1: PR54.1 PU190.31(EN)
PVDDQ_CD_EN2: PR55.1 PU197.31(EN)
PVDDQ_CD_FAULT: PR2036.1 PU19.38(FAULT1)
PVDDQ_CD_GH1: PTP32.1 PU190.6(GH)
PVDDQ_CD_GH2: PTP46.1 PU197.6(GH)
PVDDQ_CD_GL1: PTP31.1 PU190.27(GL#27)
PVDDQ_CD_GL2: PTP45.1 PU197.27(GL#27)
PVDDQ_CD_IMON: PTP4.1 PU19.20(IMON/FAULT2)
PVDDQ_CD_ISEN1N: PC7333.2 PR6651.2 PU19.28(ISEN1N)
PVDDQ_CD_ISEN1P: PC7333.1 PG70.1 PU19.29(ISEN1P)
PVDDQ_CD_ISEN2N: PC7334.2 PR6666.2 PU19.25(ISEN2N)
PVDDQ_CD_ISEN2P: PC7334.1 PG72.1 PU19.26(ISEN2P)
PVDDQ_CD_PG: PR2030.2 PR2033.2 PU19.7(VR_READY)
PVDDQ_CD_PHASE1: PC1536.2 PU190.7(PHASE)
PVDDQ_CD_PHASE1_R: PC1536.1 PR2267.2
PVDDQ_CD_PHASE2: PC1526.2 PU197.7(PHASE)
PVDDQ_CD_PHASE2_R: PC1526.1 PR2270.2
PVDDQ_CD_PWM1: PU19.4(PWM1) PU190.1(PWM)
PVDDQ_CD_PWM2: PU19.5(PWM2) PU197.1(PWM)
PVDDQ_CD_SADDR_L: PR2041.2 PU19.24(SADDR_L)
PVDDQ_CD_SADDR_M: PR2040.2 PU19.21(SADDR_M)
PVDDQ_CD_SW#1: PG66.2 PL87.1(S) PU190.16(SW#16) PU190.17(SW#17) PU190.18(SW#18) PU190.19(SW#19) PU190.20(SW#20) PU190.21(SW#21) PU190.22(SW#22) PU190.23(SW#23) PU190.24(NC#24) PU190.25(NC#25) PU190.26(NC#26)
PVDDQ_CD_SW#1_N: PG66.1 PR6652.2
PVDDQ_CD_SW#1_R: PR6651.1 PR6652.1
PVDDQ_CD_SW#2: PG71.2 PL94.1(S) PU197.16(SW#16) PU197.17(SW#17) PU197.18(SW#18) PU197.19(SW#19) PU197.20(SW#20) PU197.21(SW#21) PU197.22(SW#22) PU197.23(SW#23) PU197.24(NC#24) PU197.25(NC#25) PU197.26(NC#26)
PVDDQ_CD_SW#2_N: PG71.1 PR6665.2
PVDDQ_CD_SW#2_R: PR6665.1 PR6666.1
PVDDQ_CD_TMON1: PR36.1 PU190.30(PHFLT#)
PVDDQ_CD_TMON2: PR37.1 PU197.30(PHFLT#)
PVDDQ_CD_TSEN: PC1621.2 PR1939.1 PU19.27(TSEN)
PVDDQ_CD_TSEN_R: PC1467.2 PQ12.E PR1939.2
PVDDQ_CD_VADDR: PR2043.2 PU19.17(VADDR)
PVDDQ_CD_VCC1: PC1543.2 PR2211.2 PR2246.2 PU190.3(VCC)
PVDDQ_CD_VCC2: PC1533.2 PR2244.2 PR2245.2 PU197.3(VCC)
PVDDQ_CD_VCLK: PR2053.1 PU19.11(VCLK)
PVDDQ_CD_VD15: PC1392.1 PC1393.1 PU19.40(VD15)
PVDDQ_CD_VDD: PC1390.1 PC1391.1 PR2025.2 PU19.31(VDD)
PVDDQ_CD_VDIO: PR2052.1 PU19.12(VDIO)
PVDDQ_CD_VIN: PC391.1 PC393.1 PC396.1 PC397.1 PC1527.1 PC1528.1 PC1529.1 PC1530.1 PC1531.1 PC1532.1 PC1537.1 PC1538.1 PC1539.1 PC1540.1 PC1541.1 PC1542.1 PR2023.2 PU23.2(D1#2) PU23.3(D1#3) PU23.4(D1#4) PU23.9(D1#9) PU190.8(VIN) PU190.9(VIN) PU190.10(VIN) PU190.11(VIN) PU190.33(VIN) PU197.8(VIN) PU197.9(VIN) PU197.10(VIN) PU197.11(VIN) PU197.33(VIN) ; also on sheet 23
PVDDQ_CD_VINSEN: PC1389.1 PR2023.1 PR2024.1 PU19.30(VINSEN)
PVDDQ_CD_VSENN: PC1397.2 PR2037.2 PU19.19(VSENN)
PVDDQ_CD_VSENN_R: PR2037.1 ; also on sheet 23
PVDDQ_CD_VSENP: PC1397.1 PR2034.1 PU19.18(VSENP)
PVDDQ_CD_VSENP_R: PR2034.2 ; also on sheet 23
PVDDQ_CD_ZCD#1: PR2246.1 PU190.2(NC#2)
PVDDQ_CD_ZCD#2: PR2245.1 PU197.2(NC#2)
FM_VPP_MEM_ABCD_EN: PR186.1 ; also on sheet 22 51
IRQ_PVDDQ_CD_VRHOT_LVT3_N: PR2031.2 PU19.39(VR_HOT#) ; also on sheet 177 181
PVPP_AB: PC345.1 PC347.1 PC348.1 PC349.1 PC350.1 PC351.1 PC352.1 PC353.1 PC354.1 PD22.K(CATHODE) PL18.2(F) PR189.1 ; also on sheet 98 116 117 118 119 160
PVPP_AB_EN: PC1035.2 PR186.2 PU18.2(EN)
PVPP_AB_LL: PC342.2 PC343.1 PL18.1(S) PR188.1 PU18.6(LL#6) PU18.7(LL#7) PU18.8(LL#8) PU18.9(LL#9) PU18.10(LL#10) PU18.11(LL#11)
PVPP_AB_LL_R: PC345.2 PC346.1 PR188.2
PVPP_AB_MODE: PR190.1 PR192.2 PU18.20(MODE)
PVPP_AB_PWRGD: PR190.2 PR643.2 PU18.3(PGOOD) ; also on sheet 31
PVPP_AB_RF: PR194.2 PR195.2 PU18.22(RF)
PVPP_AB_ROVP: PR798.1 PU18.5(ROVP)
PVPP_AB_SNB: PC343.2 PR191.1
PVPP_AB_TRIP: PR193.2 PU18.21(TRIP)
PVPP_AB_VBST: PR185.1 PU18.4(VBST)
PVPP_AB_VBST_RC: PC342.1 PR185.2
PVPP_AB_VDD: PC341.1 PR184.2 PU18.19(VDD)
PVPP_AB_VFB: PC346.2 PR196.1 PR197.1 PU18.1(VFB)
PVPP_AB_VFB_R: PR189.2 PR196.2
PVPP_AB_VIN: PC336.1 PC337.1 PC338.1 PC339.1 PC340.1 PL17.2 PU18.12(VIN) PU18.13(VIN) PU18.14(VIN) PU18.15(VIN) PU18.16(VIN) PU18.17(VIN)
PVPP_AB_VREG: PC344.2 PR194.1 PU18.18(VREG)
PVPP_CD_PWRGD: PR2032.1 ; also on sheet 22
PVTT_CD: PC400.1 PC401.1 PC402.1 PC403.1 PC404.1 PC405.1 PC406.1 PC407.1 PC408.1 PC409.1 PC410.1 PC411.1 PC412.1 PC413.1 PC414.1 PG32.2 PL21.2(S) PR252.1 PR254.1 ; also on sheet 112 113 114 115
PVTT_CD_BISEN_N: PR250.2 PR251.1
PVTT_CD_BISEN_N_R: PG31.1 PR250.1
PVTT_CD_BISENN: PC1398.2 PR251.2 PR2042.2 PU19.33(BISENN)
PVTT_CD_BISENP: PC1398.1 PG32.1 PR2042.1 PU19.34(BISENP)
PVTT_CD_BPWM: PU19.2(BPWM) PU22.4(PWM)
PVTT_CD_BST: PC398.1 PU22.2(BOOT)
PVTT_CD_BTSEN: PC1402.2 PR2045.2 PU19.32(BTSEN)
PVTT_CD_BTSEN_R: PC399.2 PQ6.E PR2045.1
PVTT_CD_BVSENN: PC1400.2 PR2046.2 PU19.35(BVSENN)
PVTT_CD_BVSENP: PC1400.1 PR2044.1 PU19.36(BVSENP)
PVTT_CD_LGATE: PR854.2 PU22.6(LGATE)
PVTT_CD_LGATE_R: PR854.1 PU23.8(G2)
PVTT_CD_PH: PC398.2 PG31.2 PL21.1(F) PR246.2 PU22.10(PHASE) PU23.10(S1/D2)
PVTT_CD_PVCC: PC388.1 PC389.1 PR244.2 PU22.7(VCC) PU22.9(PVCC)
PVTT_CD_RT: PR247.2 PU22.8(RT)
PVTT_CD_UGATE: PR246.1 PR855.2 PU22.1(UGATE)
PVTT_CD_UGATE_R: PR855.1 PU23.1(G1)
PVTT_CD_VSENN_R: PR253.2 PR2046.1
PVTT_CD_VSENP_R: PR252.2 PR2044.2
PWRGD_PVPP_PVDDQ_CD: PR2033.1 ; also on sheet 51
SMB_VR_STBY_LVC3_CLK: PU19.10(SCL) ; also on sheet 16 21 31 35 39 74 161
SMB_VR_STBY_LVC3_DATA: PU19.9(SDA) ; also on sheet 16 21 31 35 39 74 161
SVID_ALERT_CPU0_N: PR2047.2 PR2051.2 ; also on sheet 31 39 139
SVID_CLK_CPU0: PR2049.2 PR2053.2 ; also on sheet 31 39 139
SVID_DIO_CPU0: PR2048.2 PR2052.2 ; also on sheet 31 39 139
VR_FAIL_PVCC_CPU_N: PR2036.2 ; also on sheet 16 21 31 35 39 74

Not connected (* = marked no-connect by the designer): PU19 3(DR_EN)* 6(PWM3)* 14(RESET#)* 15(DNC#15)* 16(DNC#16)* 23(ISEN3P)*; PU22 3(THW#)*; PU190 35(GL#35)*; PU197 35(GL#35)*

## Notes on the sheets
sheet 24
- Power rail : PVTT_CD
  Controller : PX3244H+PX3517+BSZ0907
  TDC : 2A
  Max : 3.6A
  OCP : 6A
  Sinking/Souring : +/-1.14A
  Max Transient Sinking : -1.02A
  Max Transient Sourcing : +0.46A
  Slew rate : 4.67A
  Step Size : 1.48A
- FAB1 REV013 20150413
- Change to 63.00000.00L
- FAB1 REV008 20150326
- Differential Pair
- Place near PL21
- Differential Pair
- Place at the middle of the central DIM
- Routed As Differential Pair
- Place After Lout
- Memory Slot Capacitors
- Place Capcitors Under Output Inductors on Bottom Side
sheet 25
- PVDDQ_CD_MOSFET
- FP1007R3-R15-R
  150nH/0.29mohm/61A
  7.8*10.2*7.3 mm
- FP1007R3-R15-R
  150nH/0.29mohm/61A
  7.8*10.2*7.3 mm
sheet 26
- Power rail : PVDDQ_CD
  Controller : PX3244H
  Min current : 2.59A
  TDC : 36.93A
  Max : 37.87A
  Step Size : 35.28A
  Slew rate : 16.72 A/us
  OCP : 46A
  I2C address : 0C
  SVID address : 04
  DDR Type : LR-DIMM
  Level : DDR4
  Process (nm Technology) : 2x
  Physical Rank : 4
  DRAM width : x4
  Speed (MHz) : 2400
  DRAM tech : 4Gb
  DPC (DIMM Per Channel) : 2
  Page : open
  Burst Length : 8
  # of CH/Skt used :4
  Refresh : 2x
  # Memory CHs/VR for VDD/VTT : 2
  # Memory CHs/VR for VPP : 2
- Routed As Differential Pair
- close Phase 1 between phase 2
- Routed As Differential Pair
- VDDQ Measurement point for Bode
- Routed As Differential Pair
- PVDDQ_CD I2C address:0C
- Routed As Differential Pair
- PVDDQ_CD SVID address:04
- Use Daisy Chian
- PDG P.252
- Vtt Measurement point for Bode
- Routed As Differential Pair
- Routed As Differential Pair
sheet 27
- Power rail : PVPP_AB(2V5)
  Controller : TPS53318 (Fswitching=500KHz)
  TDC : 3.24A
  MAX : 6.6A
  OCP : 8.5A
- I_rated=6A
  DCR=20mohm
  Z=22ohm
- TDK SPM6530T-2R2M
  L=2.2uH, DCR=17.3 mohm,
- FCCM Mode
- SS=5.6ms
- OCP =8.5A
- FS=500KHz
- Vout=0.6x(1+Ru/Rd)=2.496V
sheet 28
- PVDDQ_AB Decoupling
- PVDDQ_AB LC Filter
- Place Capcitors Under Output Inductors on Bottom Side
- Place After Lout
- Place in CPU Socket Cavity
- Routed As Differential Pair
- Memory Slot Capacitors
